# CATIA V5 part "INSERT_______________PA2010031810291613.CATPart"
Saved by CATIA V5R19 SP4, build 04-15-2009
Part number: INSERT_______________PA2010031810291613
Bounding box of the stored display mesh (mm): x -2.499 to 2.499, y -2.5 to 2.5, z -6 to 0
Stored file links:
  E:\CadInnWork\InWork\INSERT_______________PA2010031810291613.CATPart
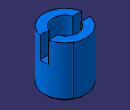
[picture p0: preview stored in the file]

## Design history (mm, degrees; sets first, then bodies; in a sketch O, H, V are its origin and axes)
Parameters
  Update = false
  PDM_version = "A"
  PDM_iteration = 1
  PDM_owner = "moren                    "
  PDM_comment = ""
  PDM_partnumber = "PA002170EA6A57201003181029160013"
Body1 (main body)
  Sketch1 on yz-plane, origin (0, 0, 0), H (0, 1, 0), V (0, 0, 1)
    axis line L1 (0, 68.5939) -> (0, -92.8528)
    point P1 (0, 68.5939)
    line L2 (0, 0) -> (2.5, 0)
    line L3 (2.5, 0) -> (2.5, -6)
    line L4 (2.5, -6) -> (0, -6)
    point P5 (0, -6)
    "Radius" L3 L1 = 2.5
    length L3 = 6
    coincidence: P1 V, P5 V
    vertical: L1 V, L3 V
    horizontal: L2 H, L4 H
  Shaft1: profile Sketch1, axis Sketch1.L1, angle 360
  Chamfer1: length 0.25, angle 45, on face of Shaft1 from Sketch1.L4
  Sketch2 on face of Shaft1 from Sketch1.L2, origin (0.3635, 1.8087, 0), H (1, 0, 0), V (0, 1, 0)
    point P1 (-0.3635, -1.8087)
    reference projected circle E1 centre (-0.3635, -1.8087) radius 2.5 from edge [face of Shaft1 from Sketch1.L2 | face of Shaft1 from Sketch1.L3]
    concentricity: E1 P1
  Hole1: placed by Sketch2, at (0, 0, 0) direction (0, 0, -1), diameter 3, through (limit type 3)
  Sketch3 on face of Shaft1 from Sketch1.L2, origin (0, 0, 0), H (1, 0, 0), V (0, 1, 0)
    line L1 (-3.4085, 0.5) -> (3.4085, 0.5)
    line L2 (3.4085, 0.5) -> (3.4085, -0.5)
    line L3 (3.4085, -0.5) -> (-3.4085, -0.5)
    line L4 (-3.4085, -0.5) -> (-3.4085, 0.5)
    reference intersected line E1 through (0, 0) direction (-1, 0) from zx-plane
    reference intersected line E2 through (0, 0) direction (0, 1) from yz-plane
    distance L1 L3 = 1
    horizontal: L1 H, L3 H
    vertical: L2 V, L4 V
    symmetry: L3 L1 E1, L2 L4 E2
  Pocket1: profile Sketch3, direction (0, 0, -1), length 2.5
